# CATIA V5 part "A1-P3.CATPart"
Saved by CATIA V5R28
Part number: Part3
Source: Unknown
Bounding box of the stored display mesh (mm): x -50 to 50, y -10 to 10, z -10 to 10
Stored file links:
  E:\TP Catia - Documents\Additional Exercise\Contrôle\Problem-3-Section-J\A1-P3.CATPart
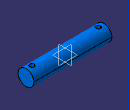
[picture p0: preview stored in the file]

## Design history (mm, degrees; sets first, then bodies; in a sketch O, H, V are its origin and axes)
Body1 (main body)
  Solid1 "Corps principal": solid without history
